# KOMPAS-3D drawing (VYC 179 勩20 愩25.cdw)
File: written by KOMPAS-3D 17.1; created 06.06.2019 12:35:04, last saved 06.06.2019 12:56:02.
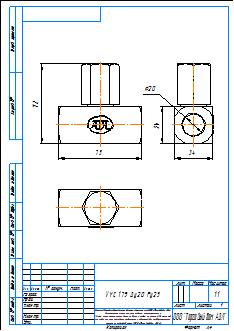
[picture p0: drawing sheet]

Sheet 1: A4, portrait

Title block, sheet 1: name: VYC 179 Ду20 Ру25; material: Внимание! Данный продукт является объектом авторского права ООО «Торговый Дом АДЛ». / Запрещается изменение, копирование, распространение / (в том числе путем копирования на другие сайты и ресурсы в Интернете) / или любое иное использование информации и объектов без предварительного / согласия правообладателя (ООО «Торговый Дом АДЛ»).; sheets: 1; organisation: ООО "Торговый дом АДЛ"; sheet format: A4; stored path: \\adlc.lan\data\АДЛ_ПКД\3D-модели\Поставщики\VYC Industrial\VYC 179\KOMPAS 2D\VYC 179 Ду20 Ру25.cdw

Views: Вид 1, Проекционный вид 2, Проекционный вид 3
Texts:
  user
Dimensions and other numbers on the sheet: 75; 72; 34; 20; 1:1; 1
